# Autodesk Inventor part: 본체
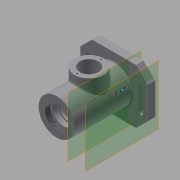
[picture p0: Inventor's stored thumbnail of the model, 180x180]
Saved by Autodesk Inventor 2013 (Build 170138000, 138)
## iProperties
Created: 2017-10
Part Number: 본체
Material: 일반
Document SubType Name: Modeling
Designer: Windows7
Density: 1 g/cm^3
Author: Windows7
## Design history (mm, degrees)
sketch "스케치1"
  geometry: L1 (58, -47)-(-58, -47); L2 (-58, -47)-(-58, 47); L3 (-58, 47)-(58, 47); L4 (58, 47)-(58, -47); L5 (58, -47)-(-58, 47); L6 (-58, -47)-(58, 47); L7 (-50, 20)-(-50, -20); L8 (-42, -20)-(-42, 20); L9 (0, 47)-(0, -47); L10 (-58, -47)-(58, 47); L11 (58, -47)-(-58, 47); L12 (50, 20)-(50, -20); L13 (42, -20)-(42, 20); A1 r 4 centre (-46, 20) between (-42, 20) and (-50, 20); A2 r 4 centre (-46, -20) between (-50, -20) and (-42, -20); A3 r 4 centre (46, 20) between (50, 20) and (42, 20); A4 r 4 centre (46, -20) between (42, -20) and (50, -20); 1 further point
  constraints: 26 end point, 10 symmetric about line, 8 point on circle, 4 centre point, 4 midpoint, 3 parallel, 2 tangent, 1 horizontal, 1 perpendicular, 2 other
  dimensions: "d0" = 116 distance of L2.end L3.end; "d1" = 94 distance of L1.end L2.end; "d5" = 8 diameter of A1; "d6" = 8 diameter of A2
extrude "돌출1" new body sketch "스케치1" distance "d7" = 13; taper "d8" = 0 deg
chamfer "모따기1" distance "d9" = 20; stored, may be unused: second distance "d10" = 2, angle "d11" = 45 deg
sketch "스케치2"
  geometry: C1 r 35 at (0, 0); 1 further point
  constraints: 1 centre point, 1 coincident
  dimensions: "d12" = 70 diameter of C1
extrude "돌출2" join sketch "스케치2" distance "d13" = 3; taper "d14" = 0 deg
extrude "돌출3" cut sketch "스케치1" distance "d15" = 13; taper "d16" = 0 deg
sketch "스케치3"
  geometry: C1 r 31 at (0, 0); 1 further point
  constraints: 1 centre point, 1 coincident
  dimensions: "d17" = 62 diameter of C1
extrude "돌출4" join sketch "스케치3" distance "d18" = 99; taper "d19" = 0 deg
sketch "스케치5"
  geometry: L1 (31, 112)-(-31, 112) reference; L2 (0, 112)-(56, 112); L3 (0, 112)-(0, 56); C1 r 25 at (0, 56); C2 r 16 at (0, 56); 1 further point
  constraints: 4 end point, 2 centre point, 2 coincident, 1 horizontal, 1 midpoint
  dimensions: "d22" = 50 diameter of C1; "d23" = 32 diameter of C2
extrude "돌출5" join sketch "스케치5" distance "d24" = 47; taper "d25" = 0 deg
sketch "스케치6"
  geometry: C1 r 25 at (0, 0) reference; C2 r 16 at (0, 0); 1 further point
  constraints: 1 centre point, 1 coincident
  dimensions: "d26" = 32 diameter of C2
extrude "돌출6" cut sketch "스케치6" distance "d27" = 47; taper "d28" = 0 deg
sketch "스케치7"
  geometry: L1 (112, -31)-(112, 31) reference; L2 (112, 0)-(112, -21); L3 (112, 0)-(-3, 0); L4 (0, -35)-(0, 35) reference; L5 (112, -21)-(103, -21); L6 (103, -21)-(103, -24); L7 (103, -24)-(100, -24); L8 (100, -24)-(100, -20); L9 (100, -20)-(91, -20); L10 (91, -17.5)-(87.75, -17.5); L11 (87.75, -18.5)-(86, -18.5); L12 (86, -17.5)-(75, -17.5); L13 (75, -26)-(37, -26); L14 (86, -18.5)-(86, -17.5); L15 (91, -20)-(91, -17.5); L16 (87.75, -18.5)-(87.75, -17.5); L17 (75, -26)-(75, -17.5); L18 (37, -17.5)-(26, -17.5); L19 (13, 31)-(13, -31) reference; L20 (37, -26)-(37, -17.5); L21 (26, -16.051)-(21, -16.051); L22 (26, -17.5)-(26, -16.051); L23 (21, -10)-(18.3, -10); L24 (18.3, -10)-(18.3, -12.5); L25 (18.3, -12.5)-(11, -12.5); L26 (-3, 35)-(-3, -35) reference; L27 (-3, 0)-(-3, -22); L28 (-3, -22)-(11, -16); L29 (11, -16)-(11, -12.5); L30 (21, -16.051)-(21, -10); 1 further point
  constraints: 52 end point, 7 parallel, 7 perpendicular, 2 midpoint, 2 point on line
  dimensions: "d29" = 21 distance of L2.start L2.end; "d30" = 9 distance of L2.end L5.end; "d31" = 3 distance of L5.end L6.end; "d32" = 3 distance of L6.end L7.end; "d33" = 4 distance of L7.end L8.end; "d34" = 9 distance of L8.end L9.end; "d36" = 3.25 distance of L10.start L10.end; "d38" = 1.75 distance of L11.start L11.end; "d40" = 11 distance of L12.start L12.end; "d42" = 38 distance of L13.start L13.end; "d44" = 11 distance of L18.start L18.end; "d46" = 5 distance of L21.start L21.end; "d48" = 2.7 distance of L23.start L23.end; "d49" = 2.5 distance of L23.end L24.end; "d50" = 7.3 distance of L24.end L25.end; "d52" = 22 distance of L3.end L27.end
revolve "회전1" sketch "스케치7" stored, may be unused: angle "d53" = 90 deg
sketch "스케치8"
  geometry: 2 further points
hole "구멍1" sketch "스케치8" at (0, 20.5) diameter "d55" = 2.459; stored, may be unused: countersink angle "d59" = 90 deg, drill point angle "d61" = 118 deg; dims "d56" = 6, "d57" = 4, "d58" = 2, "d60" = 8
node "작업 평면1"
fillet "모깎기1" dims "d63" = 3
sketch "스케치10"
  geometry: C1 r 21 at (0, 0) reference; C2 r 31 at (0, 0) reference; C3 r 21 at (0, 0); 1 further point
  constraints: 2 coincident, 1 centre point, 1 concentric
extrude "돌출7" join sketch "스케치10" distance "d64" = 9; taper "d65" = 0 deg
hole "구멍2" sketch "스케치10" diameter "d66" = 40.376; stored, may be unused: countersink angle "d70" = 82 deg, drill point angle "d72" = 118 deg; dims "d67" = 9, "d68" = 3.023, "d69" = 2, "d71" = 9
node "작업 평면3"
  node "작업 평면2"
sketch "스케치11"
  geometry: 3 further points
  constraints: 2 other
node "솔리드1"
mirror "대칭1"
other parameters: "d62" = -56
